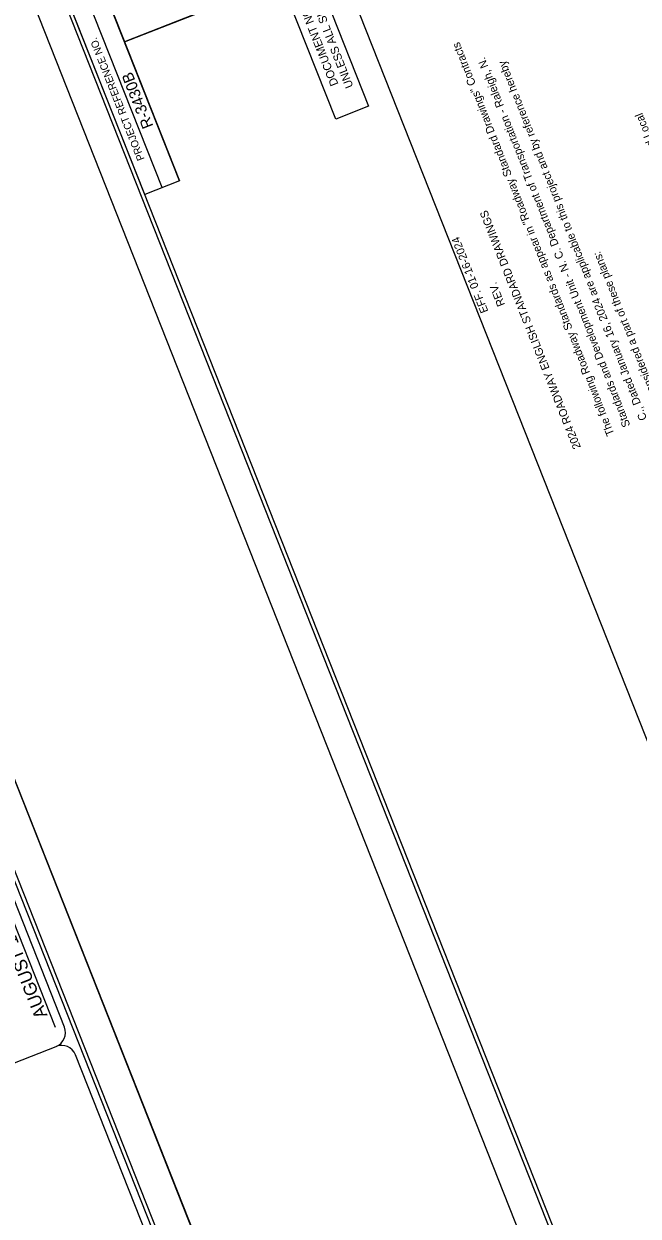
# Model space of a CAD drawing. Extents: x 1247235 to 1260080, y 742320 to 754020.
# Drawn here: x 1252768 to 1254628, y 748232 to 751842 of the extents above; entities that cross this region are included whole.
import ezdxf

# ---------------------------------------------------------------- set-up
doc = ezdxf.new("R2010")
doc.units = 0
for name, color, linetype in [('Scratch_Level_2', 7, 'Continuous'), ('Sheet Cutting Line CELL', 7, 'Continuous'), ('Sheet Data Field CELL', 7, 'Continuous'), ('Sheet Data Text CELL', 7, 'Continuous'), ('Sheet Plan CELL', 7, 'Continuous'), ('Sheet Plot Border Inside CELL', 7, 'Continuous'), ('Sheet Plot Border Outside CELL', 7, 'Continuous'), ('Sheet Sticker Exception Certification CELL', 7, 'Continuous'), ('Sheet Title CELL', 7, 'Continuous')]:
    doc.layers.add(name, color=color, linetype=linetype)

msp = doc.modelspace()

# ---------------------------------------------------------------- linework, layer by layer
at = {"layer": 'Scratch_Level_2'}
msp.add_line((1255936.1, 746431.7), (1253258.3, 753203.9), dxfattribs=at)
at = {"layer": 'Sheet Cutting Line CELL'}
msp.add_line((1254624.4, 744786.1), (1251837.9, 751833.2), dxfattribs=at)
at = {"layer": 'Sheet Plan CELL'}
for p, q in [((1253239, 751366.8), (1252906.5, 752207.8)), ((1253239, 751366.8), (1252906.5, 752207.8)), ((1253186.5, 751346), (1252854, 752187)), ((1253072.7, 751787.4), (1253545.5, 751974.3))]:
    msp.add_line(p, q, dxfattribs=at)
for points in [[(1252801.2, 752166.1), (1255294.6, 745860.4), (1259708.5, 747605.8), (1257215.2, 753911.5)], [(1253072.7, 751787.4), (1252906.5, 752207.8), (1253379.4, 752394.8), (1253545.7, 751974.4)], [(1253133.7, 751325.2), (1252801.2, 752166.1), (1252906.5, 752207.8), (1253239, 751366.8)]]:
    msp.add_lwpolyline(points, close=True, dxfattribs=at)
at = {"layer": 'Sheet Plot Border Inside CELL'}
for points in [[(1259974.2, 746964.6), (1257204.9, 753968.2), (1252769.9, 752214.5), (1255539.2, 745211)], [(1254509, 744803.4), (1251751.5, 751777.2), (1247336.2, 750031.4), (1250093.7, 743057.5)]]:
    msp.add_lwpolyline(points, close=True, dxfattribs=at)
at = {"layer": 'Sheet Plot Border Outside CELL'}
for points in [[(1260079.9, 746943.2), (1257281.5, 754020.3), (1252678.4, 752200.2), (1255476.7, 745123.1)], [(1247234.8, 750013.1), (1250021.3, 742966), (1254624.4, 744786.1), (1251837.9, 751833.2)]]:
    msp.add_lwpolyline(points, close=True, dxfattribs=at)
at = {"layer": 'Sheet Sticker Exception Certification CELL'}
for p, q in [((1253478.2, 752433.8), (1253810.7, 751592.9)), ((1253711.9, 751553.8), (1253379.4, 752394.8)), ((1253810.7, 751592.9), (1253711.9, 751553.8))]:
    msp.add_line(p, q, dxfattribs=at)
at = {"layer": 'Sheet Title CELL'}
for p, q in [((1252674, 749279.5), (1252862.2, 748803.5)), ((1252195.7, 748480.9), (1252865.2, 748745.6))]:
    msp.add_line(p, q, dxfattribs=at)
for points in [[(1254227, 745485.4), (1251778, 751678.9)], [(1252890.5, 748804), (1252419, 749996.7)], [(1253552.4, 747130.1), (1252923.7, 748720.3)]]:
    msp.add_lwpolyline(points, dxfattribs=at)
for centre, start, end in [((1252848.7, 748787.5), 291.5743, 21.5718), ((1252881.8, 748703.8), 21.5743, 111.5743)]:
    msp.add_arc(centre, 45, start, end, dxfattribs=at)

# ---------------------------------------------------------------- texts
at = {"layer": 'Sheet Data Field CELL'}
for s, height, p in [('R-3430B', 33.9, (1253160.1, 751532.8)), ('AUGUST 19, 2025', 39.375, (1252839.7, 748839.6))]:
    msp.add_text(s, height=height, rotation=111.5743, dxfattribs=at).set_placement(p)
at = {"layer": 'Sheet Data Text CELL'}
for s, p in [('The following Roadway Standards as appear in "Roadway Standard Drawings" Contracts ', (1254555.8, 750600)), ('Standards and Development Unit - N. C. Department of Transportation - Raleigh, N. ', (1254604.1, 750626.1)), ('C., Dated January 16, 2024 are applicable to this project and by reference hereby ', (1254654.8, 750646.2)), ('225.02    Guide for Grading Subgrade - Secondary and Local', (1254961.4, 750760.3)), ('2024 ROADWAY ENGLISH STANDARD DRAWINGS', (1254454.5, 750559.9)), ('                                                      EFF. 01-16-2024', (1254353.1, 750519.8)), ('are considered a part of these plans:', (1254705.5, 750666.2)), ('                                                      REV. ', (1254403.8, 750539.8))]:
    msp.add_text(s, height=24.23, rotation=111.5743, dxfattribs=at).set_placement(p)
at = {"layer": 'Sheet Plan CELL'}
msp.add_text('PROJECT REFERENCE NO.', height=22.603, rotation=111.5743, dxfattribs=at).set_placement((1253133.4, 751433))
at = {"layer": 'Sheet Sticker Exception Certification CELL'}
for s, p in [('UNLESS ALL SIGNATURES COMPLETED', (1253765.8, 751652.9)), ('DOCUMENT NOT CONSIDERED FINAL', (1253720.4, 751659.6))]:
    msp.add_text(s, height=24.863, rotation=111.5743, dxfattribs=at).set_placement(p)

doc.saveas('drawing.dxf')
